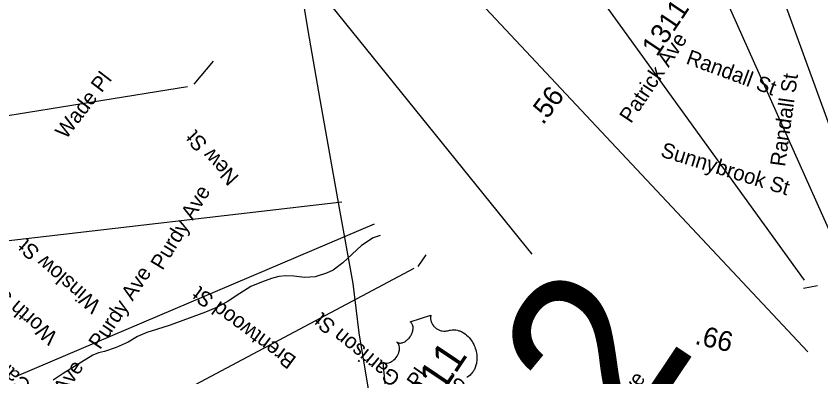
# Model space of a CAD drawing. Extents: x 1716282 to 1717158, y 799307 to 801078.
# Drawn here: x 1716607.4 to 1716680.6, y 799451.4 to 799484.2 of the extents above; entities that cross this region are included whole.
import ezdxf

# ---------------------------------------------------------------- set-up
doc = ezdxf.new("R2010")
doc.units = 0
for name, color, linetype in [('Exist Hydrographic Misc Water Feature', 7, 'Continuous'), ('Exist Road Non-System Structure Non-Sys Other Number Label', 7, 'Continuous'), ('Exist Road Non-System Type 51 Label', 7, 'Continuous'), ('Exist Road Primary Interstate Structure Cantilever Sign Number Label', 7, 'Continuous'), ('Exist Road Primary Interstate Structure Ovrhead Sign CELL', 7, 'Continuous'), ('Exist Road Primary US Mileage Hundredths English Label', 7, 'Continuous'), ('Exist Road Primary US Shield CELL', 7, 'Continuous'), ('Exist Road Primary US Shield Number Label', 7, 'Continuous'), ('Exist Road Primary US Structure Ovrhead Sign CELL', 7, 'Continuous'), ('Exist Road Primary US Structure Standard Bridge Number Label', 7, 'Continuous'), ('Exist Road Secondary Mileage Hundredths English Label', 7, 'Continuous'), ('Exist Road Secondary Structure Standard Bridge Number Label', 7, 'Continuous'), ('Exist Road Secondary Type 51 Number Label', 7, 'Continuous'), ('Exist Utilities Electrical Transmission Line', 7, 'Continuous')]:
    doc.layers.add(name, color=color, linetype=linetype)

msp = doc.modelspace()

# ---------------------------------------------------------------- linework, layer by layer
at = {"layer": 'Exist Hydrographic Misc Water Feature'}
msp.add_lwpolyline([(1716640.524, 799464.205), (1716639.87, 799464.019), (1716638.816, 799463.3), (1716637.962, 799462.512), (1716637.109, 799461.726), (1716636.233, 799461.06), (1716635.634, 799460.802), (1716634.592, 799460.458), (1716633.643, 799460.405), (1716632.662, 799460.514), (1716631.923, 799460.562), (1716631.285, 799460.503), (1716630.633, 799460.319), (1716629.735, 799459.983), (1716628.749, 799459.568), (1716627.761, 799458.943), (1716626.61, 799458.184), (1716625.581, 799457.656), (1716624.636, 799457.249), (1716621.413, 799456.078), (1716620.177, 799455.658), (1716619.289, 799455.386), (1716618.456, 799455.041), (1716617.613, 799454.528), (1716616.514, 799454.049), (1716615.439, 799453.659), (1716614.899, 799453.537), (1716614.373, 799453.333), (1716611.684, 799451.659), (1716610.792, 799451.073)], dxfattribs=at)
at = {"layer": 'Exist Road Primary Interstate Structure Cantilever Sign Number Label'}
msp.add_line((1716639.958, 799465.264), (1716607.634, 799451.502), dxfattribs=at)
at = {"layer": 'Exist Road Primary Interstate Structure Ovrhead Sign CELL'}
for p, q in [((1716679.102, 799460.155), (1716629.082, 799529.428)), ((1716679.014, 799459.439), (1716680.277, 799459.67))]:
    msp.add_line(p, q, dxfattribs=at)
at = {"layer": 'Exist Road Primary US Shield CELL'}
msp.add_lwpolyline([(1716640.963, 799450.732), (1716640.8, 799452.696), (1716640.855, 799452.664), (1716640.926, 799452.635), (1716640.966, 799452.623), (1716641.047, 799452.611), (1716641.153, 799452.61), (1716641.27, 799452.629), (1716641.384, 799452.664), (1716641.452, 799452.693), (1716641.557, 799452.749), (1716641.665, 799452.82), (1716641.771, 799452.909), (1716641.869, 799453.007), (1716641.965, 799453.121), (1716642.049, 799453.241), (1716642.127, 799453.379), (1716642.196, 799453.543), (1716642.224, 799453.622), (1716642.249, 799453.714), (1716642.266, 799453.803), (1716642.277, 799453.907), (1716642.278, 799453.995), (1716642.276, 799454.066), (1716642.256, 799454.178), (1716642.225, 799454.277), (1716642.202, 799454.325), (1716642.179, 799454.369), (1716642.12, 799454.447), (1716642.091, 799454.478), (1716642.024, 799454.53), (1716642.086, 799454.495), (1716642.127, 799454.476), (1716642.17, 799454.462), (1716642.219, 799454.451), (1716642.292, 799454.442), (1716642.357, 799454.442), (1716642.463, 799454.454), (1716642.52, 799454.467), (1716642.568, 799454.482), (1716642.686, 799454.529), (1716642.806, 799454.596), (1716642.861, 799454.631), (1716642.914, 799454.67), (1716642.977, 799454.722), (1716643.038, 799454.779), (1716643.094, 799454.838), (1716643.149, 799454.899), (1716643.201, 799454.966), (1716643.24, 799455.021), (1716643.286, 799455.091), (1716643.326, 799455.158), (1716643.362, 799455.229), (1716643.398, 799455.31), (1716643.425, 799455.377), (1716643.456, 799455.467), (1716643.477, 799455.554), (1716643.492, 799455.633), (1716643.503, 799455.74), (1716643.506, 799455.831), (1716643.5, 799455.903), (1716643.486, 799455.994), (1716643.46, 799456.088), (1716643.436, 799456.149), (1716643.405, 799456.201), (1716643.37, 799456.254), (1716643.327, 799456.301), (1716643.286, 799456.337), (1716643.249, 799456.364), (1716645.126, 799456.962), (1716645.118, 799456.924), (1716645.105, 799456.831), (1716645.101, 799456.754), (1716645.104, 799456.625), (1716645.113, 799456.564), (1716645.123, 799456.503), (1716645.137, 799456.442), (1716645.152, 799456.388), (1716645.179, 799456.317), (1716645.208, 799456.249), (1716645.243, 799456.178), (1716645.276, 799456.122), (1716645.353, 799456.013), (1716645.405, 799455.951), (1716645.453, 799455.902), (1716645.557, 799455.81), (1716645.609, 799455.77), (1716645.662, 799455.734), (1716645.721, 799455.699), (1716645.779, 799455.668), (1716645.843, 799455.64), (1716645.899, 799455.615), (1716645.971, 799455.59), (1716646.057, 799455.565), (1716646.144, 799455.547), (1716646.295, 799455.531), (1716646.459, 799455.531), (1716646.558, 799455.542), (1716646.648, 799455.558), (1716646.768, 799455.593), (1716646.834, 799455.61), (1716646.916, 799455.626), (1716647.063, 799455.644), (1716647.129, 799455.647), (1716647.2, 799455.647), (1716647.271, 799455.644), (1716647.346, 799455.637), (1716647.409, 799455.63), (1716647.549, 799455.601), (1716647.678, 799455.563), (1716647.744, 799455.54), (1716647.886, 799455.48), (1716647.954, 799455.448), (1716648.083, 799455.375), (1716648.232, 799455.277), (1716648.365, 799455.171), (1716648.511, 799455.035), (1716648.595, 799454.947), (1716648.687, 799454.837), (1716648.764, 799454.738), (1716648.871, 799454.582), (1716648.942, 799454.459), (1716649.021, 799454.308), (1716649.065, 799454.212), (1716649.109, 799454.105), (1716649.157, 799453.976), (1716649.202, 799453.831), (1716649.243, 799453.667), (1716649.268, 799453.54), (1716649.291, 799453.38), (1716649.3, 799453.286), (1716649.307, 799453.156), (1716649.307, 799452.986), (1716649.296, 799452.824), (1716649.281, 799452.691), (1716649.26, 799452.578), (1716649.227, 799452.436), (1716649.153, 799452.212), (1716649.121, 799452.133), (1716649.079, 799452.044), (1716649.035, 799451.962), (1716648.99, 799451.885), (1716648.923, 799451.785), (1716648.849, 799451.691), (1716648.773, 799451.606), (1716648.687, 799451.522), (1716648.589, 799451.441), (1716648.49, 799451.372), (1716648.381, 799451.309)], dxfattribs=at)
at = {"layer": 'Exist Road Primary US Structure Ovrhead Sign CELL'}
for p, q in [((1716623.587, 799477.972), (1716625.369, 799480.067)), ((1716622.988, 799477.746), (1716588.366, 799472.147)), ((1716643.984, 799461.388), (1716644.698, 799462.455)), ((1716643.573, 799461.232), (1716615.223, 799446.15))]:
    msp.add_line(p, q, dxfattribs=at)
at = {"layer": 'Exist Road Primary US Structure Standard Bridge Number Label'}
for p, q in [((1716684.825, 799456.904), (1716642.845, 799550.908)), ((1716688.898, 799453.424), (1716660.168, 799532.74)), ((1716679.401, 799453.638), (1716625.661, 799510.959)), ((1716654.341, 799462.534), (1716626.546, 799496.937))]:
    msp.add_line(p, q, dxfattribs=at)
at = {"layer": 'Exist Road Secondary Structure Standard Bridge Number Label'}
msp.add_line((1716637.023, 799467.254), (1716587.112, 799461.446), dxfattribs=at)
at = {"layer": 'Exist Utilities Electrical Transmission Line'}
msp.add_lwpolyline([(1716665.164, 799344.443), (1716665.563, 799347.513), (1716666.118, 799351.428), (1716663.285, 799358.348), (1716660.01, 799365.081), (1716656.683, 799371.286), (1716651.135, 799382.119), (1716649.283, 799393.013), (1716647.919, 799400.679), (1716645.991, 799411.31), (1716644.572, 799419.966), (1716643.666, 799425.239), (1716641.374, 799438.762), (1716638.601, 799455.36), (1716638.051, 799459.861), (1716636.812, 799466.701), (1716635.068, 799476.572), (1716633.977, 799482.851), (1716632.367, 799492.558)], dxfattribs=at)

# ---------------------------------------------------------------- texts
at = {"layer": 'Exist Road Non-System Structure Non-Sys Other Number Label'}
msp.add_text('J422', height=15.223, rotation=56.20506, dxfattribs=at).set_placement((1716644.84, 799417.365))
at = {"layer": 'Exist Road Non-System Type 51 Label'}
for s, rotation, p in [('Patrick Ave', 56.20506, (1716663.316, 799474.344)), ('Randall St', 339.73336, (1716668.241, 799479.87)), ('Wade Pl', 52.5599, (1716611.948, 799472.908)), ('Randall St', 82.01409, (1716677.33, 799470.432)), ('New St', 132.92506, (1716627.755, 799469.567)), ('Sunnybrook St', 342.87848, (1716665.935, 799471.417)), ('Purdy Ave', 58.76566, (1716620.72, 799460.986)), ('Winslow St', 139.0636, (1716615.218, 799458.056)), ('Purdy Ave', 56.20506, (1716615.038, 799453.777)), ('Worth St', 139.15735, (1716611.286, 799455.197)), ('Brentwood St', 143.52283, (1716632.985, 799453.092)), ('Garrison St', 141.01369, (1716642.461, 799451.429)), ('Carter St', 139.04889, (1716608.876, 799450.747)), ('Furlough Ave', 56.20506, (1716607.511, 799443.186)), ('Clish Pl', 55.18721, (1716641.323, 799446.426)), ('Manley St', 142.44769, (1716653.532, 799446.763)), ('Lowe Ave', 53.49878, (1716659.89, 799444.705))]:
    msp.add_text(s, height=1.3775, rotation=rotation, dxfattribs=at).set_placement(p)
at = {"layer": 'Exist Road Primary US Mileage Hundredths English Label'}
msp.add_text('.66', height=1.8125, rotation=346.55557, dxfattribs=at).set_placement((1716669.052, 799454.382))
at = {"layer": 'Exist Road Primary US Shield Number Label'}
msp.add_text('311', height=2.8275, rotation=56.20506, dxfattribs=at).set_placement((1716645.008, 799448.067))
at = {"layer": 'Exist Road Secondary Mileage Hundredths English Label'}
msp.add_text('.56', height=1.8125, rotation=53.23332, dxfattribs=at).set_placement((1716655.321, 799474.21))
at = {"layer": 'Exist Road Secondary Type 51 Number Label'}
msp.add_text('1311', height=1.8125, rotation=56.20506, dxfattribs=at).set_placement((1716665.684, 799480.404))

doc.saveas('drawing.dxf')
